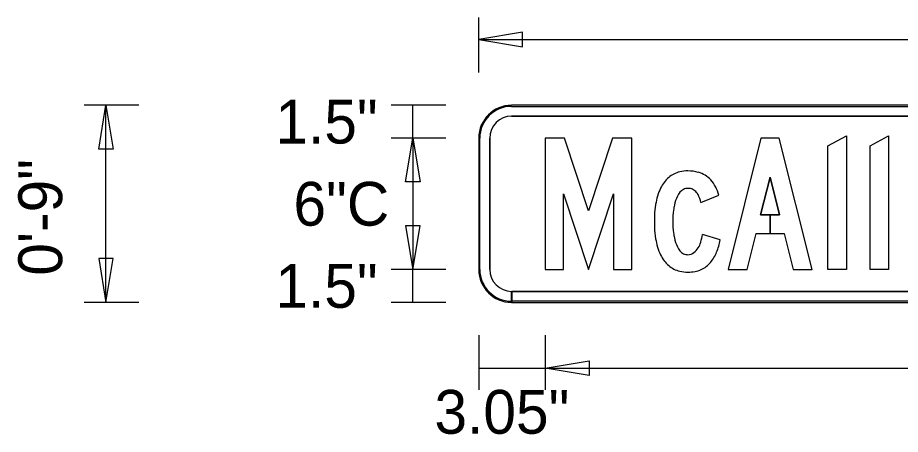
# Model space of a CAD drawing. Extents: x -875 to -645, y -2221 to -2162.
# Drawn here: x -875.229 to -871.874, y -2197.969 to -2196.383 of the extents above; entities that cross this region are included whole.
import ezdxf

# ---------------------------------------------------------------- set-up
doc = ezdxf.new("R2010")
doc.units = 0
for name, color, linetype in [('PlotBorder_dp', 7, 'Continuous'), ('SheetBorder_dp', 7, 'Continuous'), ('SheetLines_dp', 7, 'Continuous'), ('TextMinor', 7, 'Continuous')]:
    doc.layers.add(name, color=color, linetype=linetype)

msp = doc.modelspace()

# ---------------------------------------------------------------- linework, layer by layer
at = {"layer": 'PlotBorder_dp'}
for p, q in [((-869.6014, -2196.7163), (-873.3514, -2196.7163)), ((-873.3514, -2196.758), (-869.6014, -2196.758)), ((-873.4764, -2196.8413), (-873.4764, -2197.3413)), ((-873.4347, -2197.3413), (-873.4347, -2196.8413)), ((-872.6316, -2197.0869), (-872.5642, -2197.0585)), ((-872.8039, -2197.0935), (-872.8078, -2197.1262)), ((-872.8078, -2197.1914), (-872.8039, -2197.2241)), ((-872.5589, -2197.2289), (-872.6263, -2197.2076)), ((-873.3514, -2197.4663), (-873.3514, -2197.4246)), ((-869.6014, -2197.4246), (-873.351, -2197.4246)), ((-873.351, -2197.4246), (-873.351, -2197.4663)), ((-873.351, -2197.4663), (-869.6014, -2197.4663))]:
    msp.add_line(p, q, dxfattribs=at)
for points in [[(-873.0589, -2197.3413), (-872.9639, -2197.0534), (-872.9639, -2197.3413), (-872.8939, -2197.3413), (-872.8939, -2196.8413), (-872.9676, -2196.8413), (-873.0589, -2197.1179), (-873.1502, -2196.8413), (-873.2239, -2196.8413), (-873.2239, -2197.3413), (-873.1539, -2197.3413), (-873.1539, -2197.0534)], [(-872.3689, -2197.1338), (-872.4049, -2197.1338), (-872.3689, -2196.9899), (-872.3329, -2197.1338), (-872.3689, -2197.1338), (-872.3689, -2197.2038), (-872.3154, -2197.2038), (-872.2811, -2197.3413), (-872.2089, -2197.3413), (-872.3339, -2196.8413), (-872.4039, -2196.8413), (-872.5289, -2197.3413), (-872.4567, -2197.3413), (-872.4224, -2197.2038), (-872.3689, -2197.2038)], [(-872.1489, -2196.8711), (-872.0789, -2196.8325), (-872.0789, -2197.3413), (-872.1489, -2197.3413)], [(-871.9889, -2196.8711), (-871.9189, -2196.8325), (-871.9189, -2197.3413), (-871.9889, -2197.3413)]]:
    msp.add_lwpolyline(points, close=True, dxfattribs=at)
for centre, radius, start, end in [((-873.3514, -2196.8413), 0.125, 90, 180), ((-873.3514, -2196.8413), 0.0833, 90, 180), ((-872.6894, -2197.0672), 0.1, 103.3083, 130.5312), ((-872.6812, -2197.1017), 0.1354, 90, 103.3083), ((-872.6812, -2197.1143), 0.148, 74.6087, 90), ((-872.6685, -2197.068), 0.1, 42.4662, 74.6087), ((-872.6769, -2197.0819), 0.1192, 130.5312, 155.0073), ((-872.6898, -2197.0875), 0.1289, 13.0001, 42.4662), ((-872.5815, -2197.1275), 0.225, 154.7275, 171.3047), ((-872.6708, -2197.0848), 0.0553, 119.0107, 156.2962), ((-872.6812, -2197.0693), 0.0367, 90, 116.5721), ((-872.6812, -2197.0772), 0.0447, 77.0877, 90), ((-872.6791, -2197.0711), 0.0382, 50.7088, 78.1008), ((-872.6891, -2197.0815), 0.0525, 28.6423, 49.51), ((-872.581, -2197.1284), 0.1552, 154.8839, 168.1643), ((-872.7392, -2197.1093), 0.1099, 11.748, 28.8544), ((-872.4882, -2197.1479), 0.25, 168.1643, 172.5576), ((-872.3352, -2197.1588), 0.4737, 176.0579, 180), ((-872.4046, -2197.1588), 0.3343, 172.5576, 180), ((-872.3352, -2197.1588), 0.4737, 180, 183.9421), ((-872.4046, -2197.1588), 0.3343, 180, 187.4424), ((-872.4882, -2197.1697), 0.25, 187.4424, 191.8357), ((-872.808, -2197.1844), 0.1832, 343.1877, 352.722), ((-872.5815, -2197.19), 0.225, 188.6953, 205.2725), ((-872.581, -2197.1892), 0.1552, 191.8357, 205.1161), ((-872.7044, -2197.2191), 0.0741, 308.3752, 345.7436), ((-872.7997, -2197.1854), 0.2447, 338.343, 349.7655), ((-872.6708, -2197.2328), 0.0553, 203.7038, 240.9893), ((-872.6812, -2197.248), 0.037, 270, 308.0074), ((-872.7048, -2197.2233), 0.1425, 320.1081, 338.4281), ((-872.6769, -2197.2357), 0.1192, 204.9927, 229.4688), ((-872.6812, -2197.2483), 0.0367, 243.4279, 270), ((-873.3514, -2197.3413), 0.125, 180, 270), ((-873.3514, -2197.3413), 0.0833, 180, 270), ((-872.6894, -2197.2503), 0.1, 229.4688, 256.6917), ((-872.6732, -2197.2482), 0.1024, 280.7287, 294.4908), ((-872.6726, -2197.2492), 0.1012, 294.4184, 319.6313), ((-872.6812, -2197.2159), 0.1354, 256.6917, 270), ((-872.6812, -2197.2073), 0.144, 269.9997, 280.8647)]:
    msp.add_arc(centre, radius, start, end, dxfattribs=at)
at = {"layer": 'SheetBorder_dp'}
for p, q in [((-869.6014, -2196.7163), (-873.3514, -2196.7163)), ((-869.6014, -2196.7163), (-873.3514, -2196.7163)), ((-869.6014, -2196.7163), (-873.3514, -2196.7163)), ((-873.3514, -2196.7205), (-869.6014, -2196.7205)), ((-873.3514, -2196.758), (-869.6014, -2196.758)), ((-873.4764, -2196.8413), (-873.4764, -2197.3413)), ((-873.4764, -2196.8413), (-873.4764, -2197.3413)), ((-873.4764, -2196.8413), (-873.4764, -2197.3413)), ((-873.4722, -2197.3413), (-873.4722, -2196.8413)), ((-873.4347, -2197.3413), (-873.4347, -2196.8413)), ((-872.6316, -2197.0869), (-872.5642, -2197.0585)), ((-872.8039, -2197.0935), (-872.8078, -2197.1262)), ((-872.8078, -2197.1914), (-872.8039, -2197.2241)), ((-872.5589, -2197.2289), (-872.6263, -2197.2076)), ((-873.3514, -2197.4663), (-873.3514, -2197.4246)), ((-869.6014, -2197.4246), (-873.351, -2197.4246)), ((-873.351, -2197.4246), (-873.351, -2197.4663)), ((-873.3514, -2197.4663), (-873.3514, -2197.4621)), ((-869.6014, -2197.4621), (-873.3514, -2197.4621)), ((-873.3514, -2197.4621), (-873.3514, -2197.4663)), ((-873.3514, -2197.4663), (-869.6014, -2197.4663)), ((-873.3514, -2197.4663), (-869.6014, -2197.4663)), ((-873.351, -2197.4663), (-869.6014, -2197.4663))]:
    msp.add_line(p, q, dxfattribs=at)
for points in [[(-873.0589, -2197.3413), (-872.9639, -2197.0534), (-872.9639, -2197.3413), (-872.8939, -2197.3413), (-872.8939, -2196.8413), (-872.9676, -2196.8413), (-873.0589, -2197.1179), (-873.1502, -2196.8413), (-873.2239, -2196.8413), (-873.2239, -2197.3413), (-873.1539, -2197.3413), (-873.1539, -2197.0534)], [(-872.3689, -2197.1338), (-872.4049, -2197.1338), (-872.3689, -2196.9899), (-872.3329, -2197.1338), (-872.3689, -2197.1338), (-872.3689, -2197.2038), (-872.3154, -2197.2038), (-872.2811, -2197.3413), (-872.2089, -2197.3413), (-872.3339, -2196.8413), (-872.4039, -2196.8413), (-872.5289, -2197.3413), (-872.4567, -2197.3413), (-872.4224, -2197.2038), (-872.3689, -2197.2038)], [(-872.1489, -2196.8711), (-872.0789, -2196.8325), (-872.0789, -2197.3413), (-872.1489, -2197.3413)], [(-871.9889, -2196.8711), (-871.9189, -2196.8325), (-871.9189, -2197.3413), (-871.9889, -2197.3413)]]:
    msp.add_lwpolyline(points, close=True, dxfattribs=at)
for centre, radius, start, end in [((-873.3514, -2196.8413), 0.125, 90, 180), ((-873.3514, -2196.8413), 0.125, 90, 180), ((-873.3514, -2196.8413), 0.125, 90, 180), ((-873.3514, -2196.8413), 0.1208, 90, 180), ((-873.3514, -2196.8413), 0.0833, 90, 180), ((-872.6894, -2197.0672), 0.1, 103.3083, 130.5312), ((-872.6812, -2197.1017), 0.1354, 90, 103.3083), ((-872.6812, -2197.1143), 0.148, 74.6087, 90), ((-872.6685, -2197.068), 0.1, 42.4662, 74.6087), ((-872.6769, -2197.0819), 0.1192, 130.5312, 155.0073), ((-872.6898, -2197.0875), 0.1289, 13.0001, 42.4662), ((-872.5815, -2197.1275), 0.225, 154.7275, 171.3047), ((-872.6708, -2197.0848), 0.0553, 119.0107, 156.2962), ((-872.6812, -2197.0693), 0.0367, 90, 116.5721), ((-872.6812, -2197.0772), 0.0447, 77.0877, 90), ((-872.6791, -2197.0711), 0.0382, 50.7088, 78.1008), ((-872.6891, -2197.0815), 0.0525, 28.6423, 49.51), ((-872.581, -2197.1284), 0.1552, 154.8839, 168.1643), ((-872.7392, -2197.1093), 0.1099, 11.748, 28.8544), ((-872.4882, -2197.1479), 0.25, 168.1643, 172.5576), ((-872.3352, -2197.1588), 0.4737, 176.0579, 180), ((-872.4046, -2197.1588), 0.3343, 172.5576, 180), ((-872.3352, -2197.1588), 0.4737, 180, 183.9421), ((-872.4046, -2197.1588), 0.3343, 180, 187.4424), ((-872.4882, -2197.1697), 0.25, 187.4424, 191.8357), ((-872.808, -2197.1844), 0.1832, 343.1877, 352.722), ((-872.5815, -2197.19), 0.225, 188.6953, 205.2725), ((-872.581, -2197.1892), 0.1552, 191.8357, 205.1161), ((-872.7044, -2197.2191), 0.0741, 308.3752, 345.7436), ((-872.7997, -2197.1854), 0.2447, 338.343, 349.7655), ((-872.6708, -2197.2328), 0.0553, 203.7038, 240.9893), ((-872.6812, -2197.248), 0.037, 270, 308.0074), ((-872.7048, -2197.2233), 0.1425, 320.1081, 338.4281), ((-872.6769, -2197.2357), 0.1192, 204.9927, 229.4688), ((-872.6812, -2197.2483), 0.0367, 243.4279, 270), ((-873.3514, -2197.3413), 0.125, 180, 270), ((-873.3514, -2197.3413), 0.125, 180, 270), ((-873.3514, -2197.3413), 0.125, 180, 270), ((-873.3514, -2197.3413), 0.1208, 180, 270), ((-873.3514, -2197.3413), 0.0833, 180, 270), ((-872.6894, -2197.2503), 0.1, 229.4688, 256.6917), ((-872.6732, -2197.2482), 0.1024, 280.7287, 294.4908), ((-872.6726, -2197.2492), 0.1012, 294.4184, 319.6313), ((-872.6812, -2197.2159), 0.1354, 256.6917, 270), ((-872.6812, -2197.2073), 0.144, 269.9997, 280.8647)]:
    msp.add_arc(centre, radius, start, end, dxfattribs=at)
at = {"layer": 'SheetLines_dp'}
for p, q in [((-869.6014, -2196.7163), (-873.3514, -2196.7163)), ((-869.6014, -2196.758), (-873.3514, -2196.758)), ((-873.4764, -2196.8413), (-873.4764, -2197.3413)), ((-873.4347, -2196.8413), (-873.4347, -2197.3413)), ((-872.6316, -2197.0869), (-872.5642, -2197.0585)), ((-872.8039, -2197.0935), (-872.8078, -2197.1262)), ((-872.8078, -2197.1914), (-872.8039, -2197.2241)), ((-872.5589, -2197.2289), (-872.6263, -2197.2076)), ((-873.3514, -2197.4246), (-869.6014, -2197.4246)), ((-873.3514, -2197.4663), (-869.6014, -2197.4663))]:
    msp.add_line(p, q, dxfattribs=at)
for points in [[(-873.0589, -2197.3413), (-872.9639, -2197.0534), (-872.9639, -2197.3413), (-872.8939, -2197.3413), (-872.8939, -2196.8413), (-872.9676, -2196.8413), (-873.0589, -2197.1179), (-873.1502, -2196.8413), (-873.2239, -2196.8413), (-873.2239, -2197.3413), (-873.1539, -2197.3413), (-873.1539, -2197.0534)], [(-872.4224, -2197.2038), (-872.3154, -2197.2038), (-872.2811, -2197.3413), (-872.2089, -2197.3413), (-872.3339, -2196.8413), (-872.4039, -2196.8413), (-872.5289, -2197.3413), (-872.4567, -2197.3413)], [(-872.1489, -2196.8711), (-872.0789, -2196.8325), (-872.0789, -2197.3413), (-872.1489, -2197.3413)], [(-871.9889, -2196.8711), (-871.9189, -2196.8325), (-871.9189, -2197.3413), (-871.9889, -2197.3413)], [(-872.3329, -2197.1338), (-872.3689, -2196.9899), (-872.4049, -2197.1338)]]:
    msp.add_lwpolyline(points, close=True, dxfattribs=at)
for centre, radius, start, end in [((-873.3514, -2196.8413), 0.125, 90, 180), ((-873.3514, -2196.8413), 0.0833, 90, 180), ((-872.6894, -2197.0672), 0.1, 103.3083, 130.5312), ((-872.6812, -2197.1017), 0.1354, 90, 103.3083), ((-872.6812, -2197.1143), 0.148, 74.6087, 90), ((-872.6685, -2197.068), 0.1, 42.4662, 74.6087), ((-872.6769, -2197.0819), 0.1192, 130.5312, 155.0073), ((-872.6898, -2197.0875), 0.1289, 13.0001, 42.4662), ((-872.5815, -2197.1275), 0.225, 154.7275, 171.3047), ((-872.6708, -2197.0848), 0.0553, 119.0107, 156.2962), ((-872.6812, -2197.0693), 0.0367, 90, 116.5721), ((-872.6812, -2197.0772), 0.0447, 77.0877, 90), ((-872.6791, -2197.0711), 0.0382, 50.7088, 78.1008), ((-872.6891, -2197.0815), 0.0525, 28.6423, 49.51), ((-872.581, -2197.1284), 0.1552, 154.8839, 168.1643), ((-872.7392, -2197.1093), 0.1099, 11.748, 28.8544), ((-872.4882, -2197.1479), 0.25, 168.1643, 172.5576), ((-872.3352, -2197.1588), 0.4737, 176.0579, 180), ((-872.4046, -2197.1588), 0.3343, 172.5576, 180), ((-872.3352, -2197.1588), 0.4737, 180, 183.9421), ((-872.4046, -2197.1588), 0.3343, 180, 187.4424), ((-872.4882, -2197.1697), 0.25, 187.4424, 191.8357), ((-872.808, -2197.1844), 0.1832, 343.1877, 352.722), ((-872.5815, -2197.19), 0.225, 188.6953, 205.2725), ((-872.581, -2197.1892), 0.1552, 191.8357, 205.1161), ((-872.7044, -2197.2191), 0.0741, 308.3752, 345.7436), ((-872.7997, -2197.1854), 0.2447, 338.343, 349.7655), ((-872.6708, -2197.2328), 0.0553, 203.7038, 240.9893), ((-872.6812, -2197.248), 0.037, 270, 308.0074), ((-872.7048, -2197.2233), 0.1425, 320.1081, 338.4281), ((-872.6769, -2197.2357), 0.1192, 204.9927, 229.4688), ((-872.6812, -2197.2483), 0.0367, 243.4279, 270), ((-873.3514, -2197.3413), 0.125, 180, 270), ((-873.3514, -2197.3413), 0.0833, 180, 270), ((-872.6894, -2197.2503), 0.1, 229.4688, 256.6917), ((-872.6732, -2197.2482), 0.1024, 280.7287, 294.4908), ((-872.6726, -2197.2492), 0.1012, 294.4184, 319.6313), ((-872.6812, -2197.2159), 0.1354, 256.6917, 270), ((-872.6812, -2197.2073), 0.144, 269.9997, 280.8647)]:
    msp.add_arc(centre, radius, start, end, dxfattribs=at)
at = {"layer": 'TextMinor'}
for p, q in [((-873.4764, -2196.5913), (-873.4764, -2196.383)), ((-873.4764, -2196.4663), (-869.4764, -2196.4663)), ((-874.7681, -2196.7163), (-874.9764, -2196.7163)), ((-874.8931, -2197.4663), (-874.8931, -2196.7163)), ((-873.6014, -2196.7163), (-873.8097, -2196.7163)), ((-873.7264, -2196.8413), (-873.7264, -2196.7163)), ((-873.6014, -2196.8413), (-873.8097, -2196.8413)), ((-873.6014, -2196.8413), (-873.8097, -2196.8413)), ((-873.7264, -2196.8413), (-873.7264, -2197.3413)), ((-873.6014, -2197.3413), (-873.8097, -2197.3413)), ((-873.6014, -2197.3413), (-873.8097, -2197.3413)), ((-873.7264, -2197.4663), (-873.7264, -2197.3413)), ((-874.7681, -2197.4663), (-874.9764, -2197.4663)), ((-873.6014, -2197.4663), (-873.8097, -2197.4663)), ((-873.4764, -2197.5913), (-873.4764, -2197.7996)), ((-873.2239, -2197.5913), (-873.2239, -2197.7996)), ((-873.2239, -2197.5913), (-873.2239, -2197.7996)), ((-873.4764, -2197.7163), (-873.2239, -2197.7163)), ((-873.2239, -2197.7163), (-869.7289, -2197.7163))]:
    msp.add_line(p, q, dxfattribs=at)
for points in [[(-873.4764, -2196.4663), (-873.3097, -2196.4941), (-873.3097, -2196.4385)], [(-874.8931, -2196.7163), (-874.8653, -2196.883), (-874.9208, -2196.883)], [(-873.7264, -2196.8413), (-873.6986, -2197.008), (-873.7542, -2197.008)], [(-873.7264, -2197.3413), (-873.6986, -2197.1746), (-873.7542, -2197.1746)], [(-874.8931, -2197.4663), (-874.8653, -2197.2996), (-874.9208, -2197.2996)], [(-873.2239, -2197.7163), (-873.0572, -2197.6885), (-873.0572, -2197.7441)]]:
    msp.add_lwpolyline(points, close=True, dxfattribs=at)

# ---------------------------------------------------------------- texts
for s, p in [('1.5"', (-874.2492, -2196.8621)), ('6"C', (-874.1806, -2197.1746)), ('1.5"', (-874.2492, -2197.4871)), ('3.05"', (-873.6447, -2197.9663))]:
    msp.add_text(s, height=0.16667, dxfattribs=at).set_placement(p)
msp.add_text('0\'-9"', height=0.16667, rotation=90, dxfattribs=at).set_placement((-875.0597, -2197.3648))

doc.saveas('drawing.dxf')
